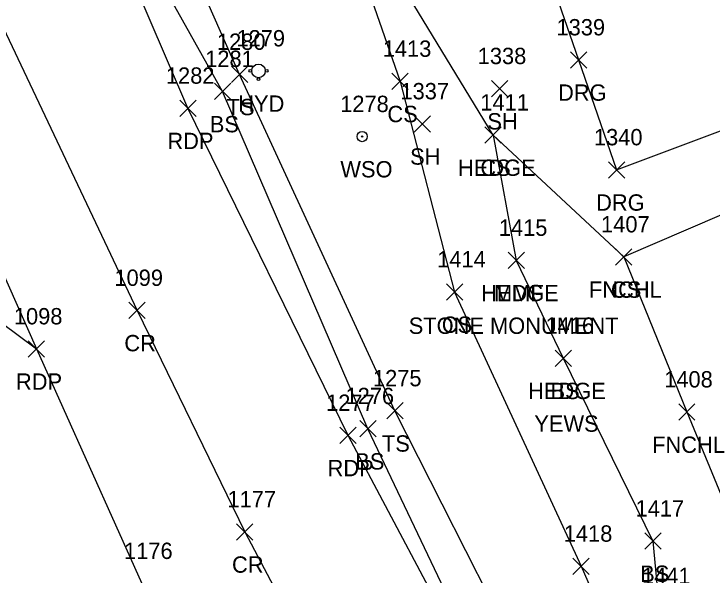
# Model space of a CAD drawing. Extents: x 1504228 to 1506103, y 437717 to 440106.
# Drawn here: x 1505127.3 to 1505212.8, y 438311.9 to 438380.6 of the extents above; entities that cross this region are included whole.
import ezdxf

# ---------------------------------------------------------------- set-up
doc = ezdxf.new("R2010")
doc.units = 0
for name, color, linetype in [('L_A', 7, 'Continuous'), ('L_C', 7, 'Continuous'), ('L_I', 7, 'Continuous'), ('L_TIC', 7, 'Continuous'), ('LAHR', 7, 'Continuous'), ('LELB', 7, 'Continuous'), ('LFNC', 7, 'Continuous'), ('P_A', 7, 'Continuous'), ('P_I', 7, 'Continuous'), ('P_TIC', 7, 'Continuous'), ('PET', 7, 'Continuous'), ('PRC', 7, 'Continuous'), ('R_A', 7, 'Continuous'), ('R_I', 7, 'Continuous'), ('R_TIC', 7, 'Continuous'), ('RDG', 7, 'Continuous'), ('U_A', 7, 'Continuous'), ('U_I', 7, 'Continuous'), ('UWFH', 7, 'Continuous'), ('UWV', 7, 'Continuous')]:
    doc.layers.add(name, color=color, linetype=linetype)

msp = doc.modelspace()

# ---------------------------------------------------------------- linework, layer by layer
at = {"layer": 'L_TIC'}
for points in [[(1505153.984, 438372.187), (1505155.984, 438374.187)], [(1505155.984, 438372.187), (1505153.984, 438374.187)], [(1505173.638, 438371.333), (1505175.638, 438373.333)], [(1505175.638, 438371.333), (1505173.638, 438373.333)], [(1505151.893, 438370.092), (1505153.893, 438372.092)], [(1505153.893, 438370.092), (1505151.893, 438372.092)], [(1505185.833, 438370.441), (1505187.833, 438372.441)], [(1505187.833, 438370.441), (1505185.833, 438372.441)], [(1505176.372, 438366.131), (1505178.372, 438368.131)], [(1505178.372, 438366.131), (1505176.372, 438368.131)], [(1505185.024, 438364.762), (1505187.024, 438366.762)], [(1505187.024, 438364.762), (1505185.024, 438366.762)], [(1505185.024, 438364.762), (1505187.024, 438366.762)], [(1505187.024, 438364.762), (1505185.024, 438366.762)], [(1505187.851, 438349.423), (1505189.851, 438351.423)], [(1505189.851, 438349.423), (1505187.851, 438351.423)], [(1505187.851, 438349.423), (1505189.851, 438351.423)], [(1505189.851, 438349.423), (1505187.851, 438351.423)], [(1505201.018, 438349.843), (1505203.018, 438351.843)], [(1505203.018, 438349.843), (1505201.018, 438351.843)], [(1505201.018, 438349.843), (1505203.018, 438351.843)], [(1505203.018, 438349.843), (1505201.018, 438351.843)], [(1505180.3, 438345.549), (1505182.3, 438347.549)], [(1505182.3, 438345.549), (1505180.3, 438347.549)], [(1505193.619, 438337.444), (1505195.619, 438339.444)], [(1505195.619, 438337.444), (1505193.619, 438339.444)], [(1505193.619, 438337.444), (1505195.619, 438339.444)], [(1505195.619, 438337.444), (1505193.619, 438339.444)], [(1505173.004, 438331.007), (1505175.004, 438333.007)], [(1505175.004, 438331.007), (1505173.004, 438333.007)], [(1505208.751, 438330.862), (1505210.751, 438332.862)], [(1505210.751, 438330.862), (1505208.751, 438332.862)], [(1505169.699, 438328.821), (1505171.699, 438330.821)], [(1505171.699, 438328.821), (1505169.699, 438330.821)], [(1505204.596, 438315.065), (1505206.596, 438317.065)], [(1505206.596, 438315.065), (1505204.596, 438317.065)], [(1505195.806, 438311.986), (1505197.806, 438313.986)], [(1505197.806, 438311.986), (1505195.806, 438313.986)]]:
    msp.add_lwpolyline(points, dxfattribs=at)
at = {"layer": 'LAHR'}
msp.add_lwpolyline([(1505186.024, 438365.762), (1505188.851, 438350.423), (1505194.619, 438338.444)], dxfattribs=at)
at = {"layer": 'LELB'}
for points in [[(1505214.51, 438265.1), (1505208.746, 438268.567), (1505200.109, 438279.294), (1505188.464, 438303.446), (1505174.004, 438332.007), (1505154.984, 438373.187), (1505140.379, 438406.193), (1505146.649, 438417.334)], [(1505202.018, 438350.843), (1505186.024, 438365.762), (1505164.75, 438400.714), (1505174.638, 438372.333), (1505181.3, 438346.549), (1505196.806, 438312.986), (1505203.883, 438296.742), (1505204.401, 438293.176), (1505213.188, 438271.582), (1505217.537, 438273.742)], [(1505195.104, 438276.759), (1505184.157, 438301.512), (1505170.699, 438329.821), (1505152.893, 438371.092), (1505139.715, 438394.629)], [(1505194.619, 438338.444), (1505205.596, 438316.065), (1505206.383, 438307.803)]]:
    msp.add_lwpolyline(points, dxfattribs=at)
at = {"layer": 'LFNC'}
msp.add_lwpolyline([(1505299.769, 438352.889), (1505273.087, 438365.446), (1505269.302, 438379.463), (1505244.766, 438368.923), (1505241.428, 438367.765), (1505202.018, 438350.843), (1505209.751, 438331.862), (1505219.874, 438307.319), (1505221.324, 438304.226)], dxfattribs=at)
at = {"layer": 'P_TIC'}
for points in [[(1505147.647, 438368.04), (1505149.647, 438370.04)], [(1505149.647, 438368.04), (1505147.647, 438370.04)], [(1505141.43, 438343.291), (1505143.43, 438345.291)], [(1505143.43, 438343.291), (1505141.43, 438345.291)], [(1505129.106, 438338.585), (1505131.106, 438340.585)], [(1505131.106, 438338.585), (1505129.106, 438340.585)], [(1505129.106, 438338.585), (1505131.106, 438340.585)], [(1505131.106, 438338.585), (1505129.106, 438340.585)], [(1505167.267, 438327.998), (1505169.267, 438329.998)], [(1505169.267, 438327.998), (1505167.267, 438329.998)], [(1505154.616, 438316.19), (1505156.616, 438318.19)], [(1505156.616, 438316.19), (1505154.616, 438318.19)]]:
    msp.add_lwpolyline(points, dxfattribs=at)
at = {"layer": 'PET'}
for points in [[(1505068.915, 438479.856), (1505088.799, 438434.786), (1505098.18, 438413.38), (1505109.535, 438384.969), (1505120.749, 438360.591), (1505130.106, 438339.585), (1505143.01, 438310.872), (1505160.435, 438272.099), (1505181.323, 438230.832), (1505199.453, 438238.762), (1505211.655, 438244.29), (1505203.781, 438257.456), (1505193.868, 438276.083), (1505183.087, 438301.098), (1505168.267, 438328.998), (1505148.647, 438369.04), (1505141.294, 438386.172), (1505109.448, 438444.779), (1505106.082, 438450.67), (1505101.61, 438460.04), (1505094.486, 438475.336), (1505087.609, 438490.541)], [(1505001.775, 438421.501), (1505032.758, 438402.461), (1505059.812, 438387.625), (1505089.41, 438366.798), (1505108.599, 438355.578), (1505130.106, 438339.585)]]:
    msp.add_lwpolyline(points, dxfattribs=at)
at = {"layer": 'PRC'}
msp.add_lwpolyline([(1505079.068, 438483.546), (1505099.188, 438438.177), (1505118.696, 438394.368), (1505142.43, 438344.291), (1505155.616, 438317.19), (1505174.858, 438280.77), (1505189.016, 438255.493), (1505199.453, 438238.762)], dxfattribs=at)
at = {"layer": 'R_TIC'}
for points in [[(1505195.491, 438373.955), (1505197.491, 438375.955)], [(1505197.491, 438373.955), (1505195.491, 438375.955)], [(1505200.154, 438360.501), (1505202.154, 438362.501)], [(1505202.154, 438360.501), (1505200.154, 438362.501)]]:
    msp.add_lwpolyline(points, dxfattribs=at)
at = {"layer": 'RDG'}
msp.add_lwpolyline([(1505169.094, 438439.64), (1505176.601, 438437.44), (1505183.394, 438415.799), (1505189.115, 438396.312), (1505196.491, 438374.955), (1505201.154, 438361.501), (1505223.011, 438369.691)], dxfattribs=at)
at = {"layer": 'UWFH'}
msp.add_line((1505157.295, 438373.608), (1505157.295, 438373.608), dxfattribs=at)
for centre, radius in [((1505157.295, 438373.608), 0.833), ((1505156.295, 438373.608), 0.167), ((1505158.295, 438373.608), 0.167), ((1505157.295, 438372.608), 0.167)]:
    msp.add_circle(centre, radius, dxfattribs=at)
at = {"layer": 'UWV'}
for radius in [0.625, 0.0833]:
    msp.add_circle((1505169.99, 438365.574), radius, dxfattribs=at)

# ---------------------------------------------------------------- texts
at = {"layer": 'L_A'}
for s, p in [('TS', (1505153.394, 438368.187)), ('CS', (1505173.078, 438367.333)), ('SH', (1505185.321, 438366.441)), ('BS', (1505151.334, 438366.092)), ('SH', (1505175.86, 438362.131)), ('HEDGE', (1505181.725, 438360.762)), ('CS', (1505184.465, 438360.762)), ('FNCHL', (1505197.767, 438345.843)), ('CS', (1505200.459, 438345.843)), ('HEDGE', (1505184.551, 438345.423)), ('MMF', (1505186.134, 438345.423)), ('CS', (1505179.741, 438341.549)), ('HEDGE', (1505190.32, 438333.444)), ('BS', (1505193.06, 438333.444)), ('TS', (1505172.413, 438327.007)), ('FNCHL', (1505205.499, 438326.862)), ('BS', (1505169.14, 438324.821)), ('BS', (1505204.037, 438311.065))]:
    msp.add_text(s, height=2, dxfattribs=at).set_placement(p)
at = {"layer": 'L_C'}
for s, p in [('STONE MONUMENT', (1505175.693, 438341.423)), ('YEWS', (1505191.076, 438329.444))]:
    msp.add_text(s, height=2, dxfattribs=at).set_placement(p)
at = {"layer": 'L_I'}
for s, p in [('1280', (1505152.205, 438376.187)), ('1413', (1505172.512, 438375.333)), ('1281', (1505150.767, 438374.092)), ('1338', (1505184.14, 438374.441)), ('1337', (1505174.679, 438370.131)), ('1411', (1505184.465, 438368.762)), ('1411', (1505184.465, 438368.762)), ('1407', (1505199.247, 438353.843)), ('1407', (1505199.247, 438353.843)), ('1415', (1505186.725, 438353.423)), ('1415', (1505186.725, 438353.423)), ('1414', (1505179.174, 438349.549)), ('1416', (1505192.438, 438341.444)), ('1416', (1505192.438, 438341.444)), ('1275', (1505171.311, 438335.007)), ('1408', (1505206.979, 438334.862)), ('1276', (1505167.951, 438332.821)), ('1417', (1505203.47, 438319.065)), ('1418', (1505194.68, 438315.986)), ('1441', (1505204.257, 438310.803))]:
    msp.add_text(s, height=2, dxfattribs=at).set_placement(p)
at = {"layer": 'P_A'}
for s, p in [('RDP', (1505146.135, 438364.04)), ('CR', (1505140.863, 438339.291)), ('RDP', (1505127.594, 438334.585)), ('RDP', (1505127.594, 438334.585)), ('RDP', (1505165.755, 438323.998)), ('CR', (1505154.049, 438312.19))]:
    msp.add_text(s, height=2, dxfattribs=at).set_placement(p)
at = {"layer": 'P_I'}
for s, p in [('1282', (1505145.954, 438372.04)), ('1099', (1505139.65, 438347.291)), ('1098', (1505127.335, 438342.585)), ('1098', (1505127.335, 438342.585)), ('1277', (1505165.574, 438331.998)), ('1177', (1505153.49, 438320.19)), ('1176', (1505140.829, 438313.872))]:
    msp.add_text(s, height=2, dxfattribs=at).set_placement(p)
at = {"layer": 'R_A'}
for p in [(1505193.979, 438369.955), (1505198.643, 438356.501)]:
    msp.add_text('DRG', height=2, dxfattribs=at).set_placement(p)
at = {"layer": 'R_I'}
for s, p in [('1339', (1505193.79, 438377.955)), ('1340', (1505198.375, 438364.501))]:
    msp.add_text(s, height=2, dxfattribs=at).set_placement(p)
at = {"layer": 'U_A'}
for s, p in [('HYD', (1505154.815, 438368.608)), ('WSO', (1505167.32, 438360.574))]:
    msp.add_text(s, height=2, dxfattribs=at).set_placement(p)
at = {"layer": 'U_I'}
for s, p in [('1279', (1505154.594, 438376.608)), ('1278', (1505167.297, 438368.574))]:
    msp.add_text(s, height=2, dxfattribs=at).set_placement(p)

doc.saveas('drawing.dxf')
